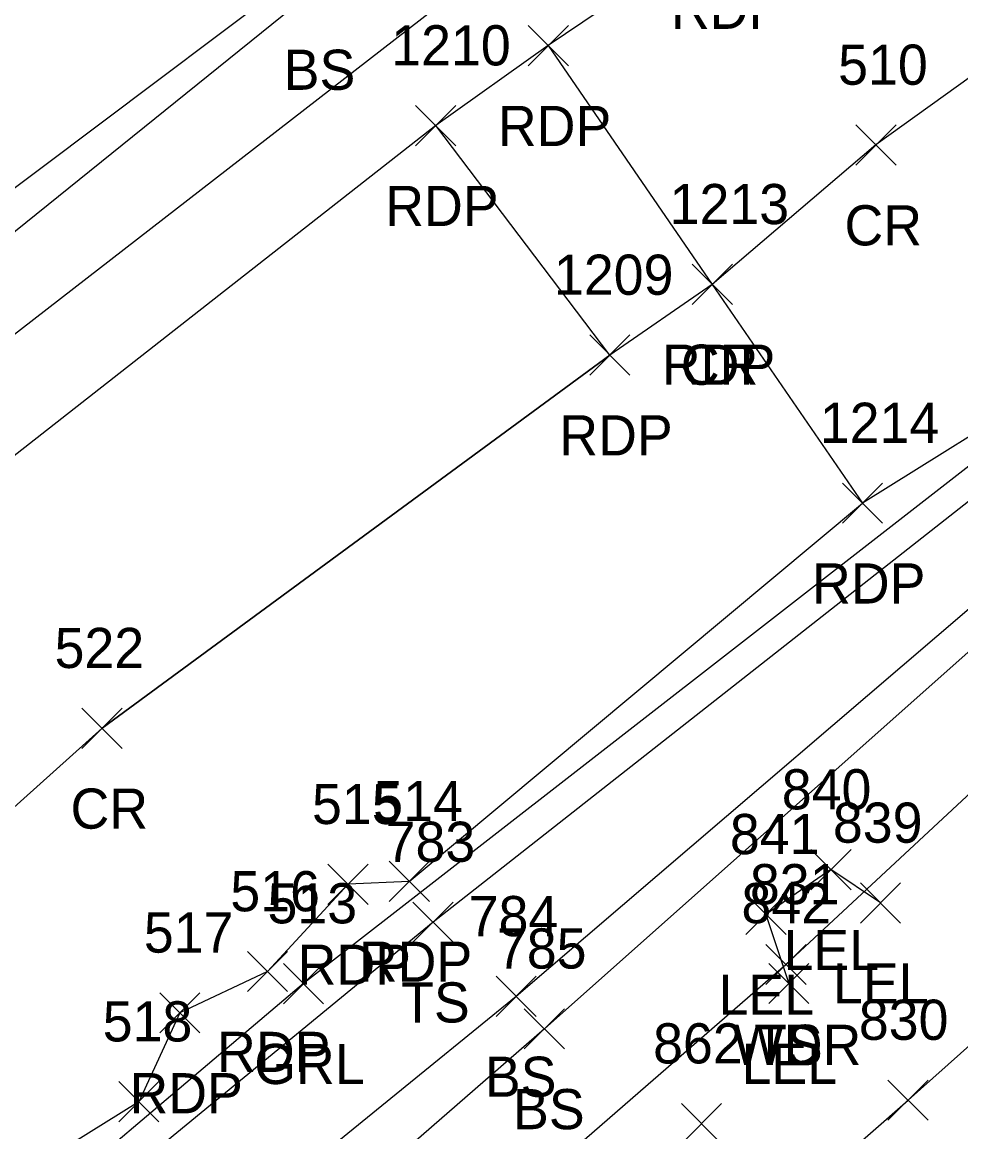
# Model space of a CAD drawing. Extents: x 1528286 to 1556263, y 492387 to 508952.
# Drawn here: x 1528541.2 to 1528588, y 492686.8 to 492742 of the extents above; entities that cross this region are included whole.
import ezdxf

# ---------------------------------------------------------------- set-up
doc = ezdxf.new("R2010")
doc.units = 0
for name, color, linetype in [('L_A', 7, 'Continuous'), ('L_I', 7, 'Continuous'), ('L_TIC', 7, 'Continuous'), ('LARO', 7, 'Continuous'), ('LAWA', 7, 'Continuous'), ('LELB', 7, 'Continuous'), ('P_A', 7, 'Continuous'), ('P_I', 7, 'Continuous'), ('P_TIC', 7, 'Continuous'), ('PET', 7, 'Continuous'), ('PRC', 7, 'Continuous'), ('R_A', 7, 'Continuous'), ('R_I', 7, 'Continuous'), ('R_TIC', 7, 'Continuous'), ('RGR', 7, 'Continuous')]:
    doc.layers.add(name, color=color, linetype=linetype)

msp = doc.modelspace()

# ---------------------------------------------------------------- linework, layer by layer
at = {"layer": 'L_TIC'}
for points in [[(1528580.51, 492698.848), (1528582.51, 492700.848)], [(1528582.51, 492698.848), (1528580.51, 492700.848)], [(1528580.51, 492698.848), (1528582.51, 492700.848)], [(1528582.51, 492698.848), (1528580.51, 492700.848)], [(1528582.976, 492697.188), (1528584.976, 492699.188)], [(1528584.976, 492697.188), (1528582.976, 492699.188)], [(1528582.976, 492697.188), (1528584.976, 492699.188)], [(1528584.976, 492697.188), (1528582.976, 492699.188)], [(1528577.273, 492696.621), (1528579.273, 492698.621)], [(1528579.273, 492696.621), (1528577.273, 492698.621)], [(1528577.273, 492696.621), (1528579.273, 492698.621)], [(1528579.273, 492696.621), (1528577.273, 492698.621)], [(1528560.7, 492696.236), (1528562.7, 492698.236)], [(1528562.7, 492696.236), (1528560.7, 492698.236)], [(1528560.7, 492696.236), (1528562.7, 492698.236)], [(1528562.7, 492696.236), (1528560.7, 492698.236)], [(1528578.271, 492694.125), (1528580.271, 492696.125)], [(1528580.271, 492694.125), (1528578.271, 492696.125)], [(1528578.271, 492694.125), (1528580.271, 492696.125)], [(1528580.271, 492694.125), (1528578.271, 492696.125)], [(1528578.271, 492694.125), (1528580.271, 492696.125)], [(1528580.271, 492694.125), (1528578.271, 492696.125)], [(1528578.271, 492694.125), (1528580.271, 492696.125)], [(1528580.271, 492694.125), (1528578.271, 492696.125)], [(1528578.416, 492693.181), (1528580.416, 492695.181)], [(1528580.416, 492693.181), (1528578.416, 492695.181)], [(1528578.416, 492693.181), (1528580.416, 492695.181)], [(1528580.416, 492693.181), (1528578.416, 492695.181)], [(1528564.837, 492692.535), (1528566.837, 492694.535)], [(1528566.837, 492692.535), (1528564.837, 492694.535)], [(1528564.837, 492692.535), (1528566.837, 492694.535)], [(1528566.837, 492692.535), (1528564.837, 492694.535)], [(1528566.241, 492690.922), (1528568.241, 492692.922)], [(1528568.241, 492690.922), (1528566.241, 492692.922)], [(1528566.241, 492690.922), (1528568.241, 492692.922)], [(1528568.241, 492690.922), (1528566.241, 492692.922)], [(1528584.347, 492687.372), (1528586.347, 492689.372)], [(1528586.347, 492687.372), (1528584.347, 492689.372)], [(1528584.347, 492687.372), (1528586.347, 492689.372)], [(1528586.347, 492687.372), (1528584.347, 492689.372)], [(1528574.065, 492686.197), (1528576.065, 492688.197)], [(1528576.065, 492686.197), (1528574.065, 492688.197)], [(1528574.065, 492686.197), (1528576.065, 492688.197)], [(1528576.065, 492686.197), (1528574.065, 492688.197)]]:
    msp.add_lwpolyline(points, dxfattribs=at)
at = {"layer": 'LARO'}
msp.add_lwpolyline([(1528583.976, 492698.188), (1528581.51, 492699.848), (1528578.273, 492697.621), (1528579.416, 492694.181)], dxfattribs=at)
msp.add_lwpolyline([(1528583.976, 492698.188), (1528581.51, 492699.848), (1528578.273, 492697.621), (1528579.416, 492694.181)], dxfattribs=at)
at = {"layer": 'LAWA'}
msp.add_lwpolyline([(1528350.567, 492486.658), (1528374.131, 492513.994), (1528413.925, 492550.925), (1528435.091, 492569.848), (1528453.537, 492583.197), (1528487.048, 492613.162), (1528503.178, 492626.813), (1528522.579, 492648.478), (1528559.072, 492677.555), (1528579.271, 492695.125), (1528598.445, 492712.961), (1528609.007, 492715.026)], dxfattribs=at)
msp.add_lwpolyline([(1528350.567, 492486.658), (1528374.131, 492513.994), (1528413.925, 492550.925), (1528435.091, 492569.848), (1528453.537, 492583.197), (1528487.048, 492613.162), (1528503.178, 492626.813), (1528522.579, 492648.478), (1528559.072, 492677.555), (1528579.271, 492695.125), (1528598.445, 492712.961), (1528609.007, 492715.026)], dxfattribs=at)
at = {"layer": 'LELB'}
for points in [[(1528511.531, 492702.846), (1528534.14, 492721.314), (1528572.642, 492751.164), (1528586.729, 492763.586), (1528600.497, 492766.346), (1528613.458, 492775.516), (1528652.2, 492802.526), (1528688.619, 492828.262), (1528710.289, 492843.118), (1528742.907, 492866.471), (1528778.713, 492891.266), (1528817.445, 492919.082), (1528857.746, 492946.937), (1528897.372, 492973.983), (1528940.286, 493003.739)], [(1528511.531, 492702.846), (1528534.14, 492721.314), (1528572.642, 492751.164), (1528586.729, 492763.586), (1528600.497, 492766.346), (1528613.458, 492775.516), (1528652.2, 492802.526), (1528688.619, 492828.262), (1528710.289, 492843.118), (1528742.907, 492866.471), (1528778.713, 492891.266), (1528817.445, 492919.082), (1528857.746, 492946.937), (1528897.372, 492973.983), (1528940.286, 493003.739)], [(1528476.47, 492733.086), (1528490.627, 492720.26), (1528499.344, 492715.307), (1528510.272, 492713.09), (1528516.407, 492713.286), (1528530.473, 492725.995), (1528568.475, 492754.562), (1528582.496, 492766.122), (1528590.696, 492769.852), (1528623.394, 492792.056), (1528660.048, 492816.01), (1528671.542, 492831.179), (1528678.095, 492847.611)], [(1528476.47, 492733.086), (1528490.627, 492720.26), (1528499.344, 492715.307), (1528510.272, 492713.09), (1528516.407, 492713.286), (1528530.473, 492725.995), (1528568.475, 492754.562), (1528582.496, 492766.122), (1528590.696, 492769.852), (1528623.394, 492792.056), (1528660.048, 492816.01), (1528671.542, 492831.179), (1528678.095, 492847.611)], [(1528685.936, 492838.575), (1528672.607, 492830.811), (1528666.617, 492820.24), (1528643.207, 492802.995), (1528614.904, 492783.769), (1528590.503, 492768.834), (1528580.049, 492763.591), (1528573.986, 492757.651), (1528555.822, 492743.679), (1528531.303, 492723.898), (1528516.93, 492710.506), (1528511.372, 492706.597)], [(1528685.936, 492838.575), (1528672.607, 492830.811), (1528666.617, 492820.24), (1528643.207, 492802.995), (1528614.904, 492783.769), (1528590.503, 492768.834), (1528580.049, 492763.591), (1528573.986, 492757.651), (1528555.822, 492743.679), (1528531.303, 492723.898), (1528516.93, 492710.506), (1528511.372, 492706.597)], [(1528627.535, 492747.197), (1528602.245, 492728.24), (1528590.919, 492720.18), (1528561.7, 492697.236), (1528528.44, 492669.894), (1528504.886, 492649.176), (1528486.55, 492633.133), (1528477.153, 492624.603), (1528462.188, 492611.303), (1528435.473, 492586.893), (1528420.499, 492573.078), (1528389.262, 492542.582), (1528363.671, 492517.292), (1528340.83, 492494.601)], [(1528627.535, 492747.197), (1528602.245, 492728.24), (1528590.919, 492720.18), (1528561.7, 492697.236), (1528528.44, 492669.894), (1528504.886, 492649.176), (1528486.55, 492633.133), (1528477.153, 492624.603), (1528462.188, 492611.303), (1528435.473, 492586.893), (1528420.499, 492573.078), (1528389.262, 492542.582), (1528363.671, 492517.292), (1528340.83, 492494.601)], [(1528608.223, 492722.999), (1528593.799, 492717.472), (1528565.837, 492693.535), (1528532.387, 492666.306), (1528510.922, 492648.814), (1528501.929, 492641.591)], [(1528608.223, 492722.999), (1528593.799, 492717.472), (1528565.837, 492693.535), (1528532.387, 492666.306), (1528510.922, 492648.814), (1528501.929, 492641.591)], [(1528608.107, 492719.723), (1528594.767, 492716.381), (1528567.241, 492691.922), (1528534.242, 492663.203), (1528520.965, 492652.416), (1528501.929, 492641.591)], [(1528608.107, 492719.723), (1528594.767, 492716.381), (1528567.241, 492691.922), (1528534.242, 492663.203), (1528520.965, 492652.416), (1528501.929, 492641.591)], [(1528495.396, 492632.327), (1528503.178, 492626.813), (1528527.225, 492642.12), (1528549.208, 492659.483), (1528567.953, 492673.117), (1528585.347, 492688.372), (1528604.063, 492705.044), (1528609.007, 492715.026)], [(1528495.396, 492632.327), (1528503.178, 492626.813), (1528527.225, 492642.12), (1528549.208, 492659.483), (1528567.953, 492673.117), (1528585.347, 492688.372), (1528604.063, 492705.044), (1528609.007, 492715.026)], [(1528507.297, 492637.674), (1528537.612, 492659.846), (1528559.072, 492677.555), (1528579.271, 492695.125), (1528598.445, 492712.961), (1528609.007, 492715.026)], [(1528507.297, 492637.674), (1528537.612, 492659.846), (1528559.072, 492677.555), (1528579.271, 492695.125), (1528598.445, 492712.961), (1528609.007, 492715.026)]]:
    msp.add_lwpolyline(points, dxfattribs=at)
at = {"layer": 'P_TIC'}
for points in [[(1528566.438, 492739.881), (1528568.438, 492741.881)], [(1528568.438, 492739.881), (1528566.438, 492741.881)], [(1528566.438, 492739.881), (1528568.438, 492741.881)], [(1528568.438, 492739.881), (1528566.438, 492741.881)], [(1528560.831, 492735.896), (1528562.831, 492737.896)], [(1528562.831, 492735.896), (1528560.831, 492737.896)], [(1528560.831, 492735.896), (1528562.831, 492737.896)], [(1528562.831, 492735.896), (1528560.831, 492737.896)], [(1528582.75, 492734.932), (1528584.75, 492736.932)], [(1528584.75, 492734.932), (1528582.75, 492736.932)], [(1528582.75, 492734.932), (1528584.75, 492736.932)], [(1528584.75, 492734.932), (1528582.75, 492736.932)], [(1528574.604, 492727.991), (1528576.604, 492729.991)], [(1528576.604, 492727.991), (1528574.604, 492729.991)], [(1528574.604, 492727.991), (1528576.604, 492729.991)], [(1528576.604, 492727.991), (1528574.604, 492729.991)], [(1528574.604, 492727.991), (1528576.604, 492729.991)], [(1528576.604, 492727.991), (1528574.604, 492729.991)], [(1528574.604, 492727.991), (1528576.604, 492729.991)], [(1528576.604, 492727.991), (1528574.604, 492729.991)], [(1528569.498, 492724.473), (1528571.498, 492726.473)], [(1528571.498, 492724.473), (1528569.498, 492726.473)], [(1528569.498, 492724.473), (1528571.498, 492726.473)], [(1528571.498, 492724.473), (1528569.498, 492726.473)], [(1528582.08, 492717.1), (1528584.08, 492719.1)], [(1528584.08, 492717.1), (1528582.08, 492719.1)], [(1528582.08, 492717.1), (1528584.08, 492719.1)], [(1528584.08, 492717.1), (1528582.08, 492719.1)], [(1528544.219, 492705.888), (1528546.219, 492707.888)], [(1528546.219, 492705.888), (1528544.219, 492707.888)], [(1528544.219, 492705.888), (1528546.219, 492707.888)], [(1528546.219, 492705.888), (1528544.219, 492707.888)], [(1528556.469, 492698.118), (1528558.469, 492700.118)], [(1528558.469, 492698.118), (1528556.469, 492700.118)], [(1528556.469, 492698.118), (1528558.469, 492700.118)], [(1528558.469, 492698.118), (1528556.469, 492700.118)], [(1528559.517, 492698.264), (1528561.517, 492700.264)], [(1528561.517, 492698.264), (1528559.517, 492700.264)], [(1528559.517, 492698.264), (1528561.517, 492700.264)], [(1528561.517, 492698.264), (1528559.517, 492700.264)], [(1528552.458, 492693.773), (1528554.458, 492695.773)], [(1528554.458, 492693.773), (1528552.458, 492695.773)], [(1528552.458, 492693.773), (1528554.458, 492695.773)], [(1528554.458, 492693.773), (1528552.458, 492695.773)], [(1528548.097, 492691.715), (1528550.097, 492693.715)], [(1528550.097, 492691.715), (1528548.097, 492693.715)], [(1528548.097, 492691.715), (1528550.097, 492693.715)], [(1528550.097, 492691.715), (1528548.097, 492693.715)], [(1528546.05, 492687.292), (1528548.05, 492689.292)], [(1528548.05, 492687.292), (1528546.05, 492689.292)], [(1528546.05, 492687.292), (1528548.05, 492689.292)], [(1528548.05, 492687.292), (1528546.05, 492689.292)]]:
    msp.add_lwpolyline(points, dxfattribs=at)
at = {"layer": 'PET'}
for points in [[(1528576.056, 492746.716), (1528567.438, 492740.881)], [(1528576.056, 492746.716), (1528567.438, 492740.881)], [(1528567.438, 492740.881), (1528561.831, 492736.896)], [(1528567.438, 492740.881), (1528561.831, 492736.896)], [(1528567.438, 492740.881), (1528575.604, 492728.991), (1528583.08, 492718.1)], [(1528567.438, 492740.881), (1528575.604, 492728.991), (1528583.08, 492718.1)], [(1528561.831, 492736.896), (1528536.991, 492717.453)], [(1528561.831, 492736.896), (1528536.991, 492717.453)], [(1528570.498, 492725.473), (1528561.831, 492736.896)], [(1528570.498, 492725.473), (1528561.831, 492736.896)], [(1528570.498, 492725.473), (1528545.219, 492706.888)], [(1528570.498, 492725.473), (1528545.219, 492706.888)], [(1528592.558, 492724.002), (1528583.08, 492718.1)], [(1528592.558, 492724.002), (1528583.08, 492718.1)], [(1528560.517, 492699.264), (1528583.08, 492718.1)], [(1528560.517, 492699.264), (1528583.08, 492718.1)], [(1528523.925, 492687.768), (1528545.219, 492706.888)], [(1528523.925, 492687.768), (1528545.219, 492706.888)], [(1528560.517, 492699.264), (1528557.469, 492699.118), (1528553.458, 492694.773), (1528549.097, 492692.715), (1528547.05, 492688.292), (1528537.757, 492682.515), (1528535.94, 492680.254), (1528535.911, 492679.061), (1528519.42, 492665.123), (1528485.647, 492635.106), (1528449.898, 492603.317), (1528443.292, 492597.221), (1528441.443, 492597.056), (1528433.939, 492590.577), (1528430.616, 492585.987), (1528412.089, 492568.516), (1528375.77, 492531.986), (1528339.078, 492496.271)], [(1528560.517, 492699.264), (1528557.469, 492699.118), (1528553.458, 492694.773), (1528549.097, 492692.715), (1528547.05, 492688.292), (1528537.757, 492682.515), (1528535.94, 492680.254), (1528535.911, 492679.061), (1528519.42, 492665.123), (1528485.647, 492635.106), (1528449.898, 492603.317), (1528443.292, 492597.221), (1528441.443, 492597.056), (1528433.939, 492590.577), (1528430.616, 492585.987), (1528412.089, 492568.516), (1528375.77, 492531.986), (1528339.078, 492496.271)]]:
    msp.add_lwpolyline(points, dxfattribs=at)
at = {"layer": 'PRC'}
for points in [[(1528622.148, 492763.521), (1528583.75, 492735.932)], [(1528622.148, 492763.521), (1528583.75, 492735.932)], [(1528583.75, 492735.932), (1528575.604, 492728.991)], [(1528583.75, 492735.932), (1528575.604, 492728.991)], [(1528575.604, 492728.991), (1528570.498, 492725.473)], [(1528575.604, 492728.991), (1528570.498, 492725.473)], [(1528545.219, 492706.888), (1528570.498, 492725.473)], [(1528545.219, 492706.888), (1528570.498, 492725.473)], [(1528545.219, 492706.888), (1528523.925, 492687.768)], [(1528545.219, 492706.888), (1528523.925, 492687.768)]]:
    msp.add_lwpolyline(points, dxfattribs=at)
at = {"layer": 'R_TIC'}
for points in [[(1528554.254, 492693.171), (1528556.254, 492695.171)], [(1528556.254, 492693.171), (1528554.254, 492695.171)], [(1528554.254, 492693.171), (1528556.254, 492695.171)], [(1528556.254, 492693.171), (1528554.254, 492695.171)]]:
    msp.add_lwpolyline(points, dxfattribs=at)
at = {"layer": 'RGR'}
msp.add_lwpolyline([(1528631.557, 492751.518), (1528593.228, 492723.7), (1528555.254, 492694.171), (1528520.288, 492664.562), (1528486.051, 492634.677), (1528450.283, 492602.919), (1528412.918, 492568.153), (1528376.626, 492531.198), (1528339.769, 492495.46)], dxfattribs=at)
msp.add_lwpolyline([(1528631.557, 492751.518), (1528593.228, 492723.7), (1528555.254, 492694.171), (1528520.288, 492664.562), (1528486.051, 492634.677), (1528450.283, 492602.919), (1528412.918, 492568.153), (1528376.626, 492531.198), (1528339.769, 492495.46)], dxfattribs=at)

# ---------------------------------------------------------------- texts
at = {"layer": 'L_A'}
for s, p in [('BS', (1528554.263, 492738.679)), ('BS', (1528554.263, 492738.679)), ('LEL', (1528579.148, 492694.848)), ('LEL', (1528579.148, 492694.848)), ('LEL', (1528581.614, 492693.188)), ('LEL', (1528581.614, 492693.188)), ('LEL', (1528575.911, 492692.621)), ('LEL', (1528575.911, 492692.621)), ('TS', (1528560.11, 492692.236)), ('TS', (1528560.11, 492692.236)), ('WDR', (1528576.634, 492690.125)), ('WDR', (1528576.634, 492690.125)), ('TS', (1528577.681, 492690.125)), ('TS', (1528577.681, 492690.125)), ('LEL', (1528577.054, 492689.181)), ('LEL', (1528577.054, 492689.181)), ('BS', (1528564.278, 492688.535)), ('BS', (1528564.278, 492688.535)), ('BS', (1528565.682, 492686.922)), ('BS', (1528565.682, 492686.922))]:
    msp.add_text(s, height=2, dxfattribs=at).set_placement(p)
at = {"layer": 'L_I'}
for s, p in [('840', (1528579.061, 492702.848)), ('840', (1528579.061, 492702.848)), ('839', (1528581.606, 492701.188)), ('839', (1528581.606, 492701.188)), ('783', (1528559.338, 492700.236)), ('783', (1528559.338, 492700.236)), ('841', (1528576.478, 492700.621)), ('841', (1528576.478, 492700.621)), ('831', (1528577.476, 492698.125)), ('831', (1528577.476, 492698.125)), ('831', (1528577.476, 492698.125)), ('831', (1528577.476, 492698.125)), ('842', (1528577.054, 492697.181)), ('842', (1528577.054, 492697.181)), ('784', (1528563.475, 492696.535)), ('784', (1528563.475, 492696.535)), ('785', (1528564.879, 492694.922)), ('785', (1528564.879, 492694.922)), ('830', (1528582.898, 492691.372)), ('830', (1528582.898, 492691.372)), ('862', (1528572.655, 492690.197)), ('862', (1528572.655, 492690.197))]:
    msp.add_text(s, height=2, dxfattribs=at).set_placement(p)
at = {"layer": 'P_A'}
for s, p in [('RDP', (1528573.544, 492741.716)), ('RDP', (1528573.544, 492741.716)), ('RDP', (1528564.926, 492735.881)), ('RDP', (1528564.926, 492735.881)), ('RDP', (1528559.319, 492731.896)), ('RDP', (1528559.319, 492731.896)), ('CR', (1528582.183, 492730.932)), ('CR', (1528582.183, 492730.932)), ('RDP', (1528573.092, 492723.991)), ('RDP', (1528573.092, 492723.991)), ('CR', (1528574.037, 492723.991)), ('CR', (1528574.037, 492723.991)), ('RDP', (1528567.986, 492720.473)), ('RDP', (1528567.986, 492720.473)), ('RDP', (1528580.568, 492713.1)), ('RDP', (1528580.568, 492713.1)), ('CR', (1528543.652, 492701.888)), ('CR', (1528543.652, 492701.888)), ('RDP', (1528554.957, 492694.118)), ('RDP', (1528554.957, 492694.118)), ('RDP', (1528558.005, 492694.264)), ('RDP', (1528558.005, 492694.264)), ('RDP', (1528550.947, 492689.773)), ('RDP', (1528550.947, 492689.773)), ('RDP', (1528546.585, 492687.715)), ('RDP', (1528546.585, 492687.715))]:
    msp.add_text(s, height=2, dxfattribs=at).set_placement(p)
at = {"layer": 'P_I'}
for s, p in [('1210', (1528559.618, 492739.896)), ('1210', (1528559.618, 492739.896)), ('510', (1528581.868, 492738.932)), ('510', (1528581.868, 492738.932)), ('1213', (1528573.478, 492731.991)), ('1213', (1528573.478, 492731.991)), ('1213', (1528573.478, 492731.991)), ('1213', (1528573.478, 492731.991)), ('1209', (1528567.719, 492728.473)), ('1209', (1528567.719, 492728.473)), ('1214', (1528580.954, 492721.1)), ('1214', (1528580.954, 492721.1)), ('522', (1528542.857, 492709.888)), ('522', (1528542.857, 492709.888)), ('515', (1528555.674, 492702.118)), ('515', (1528555.674, 492702.118)), ('514', (1528558.722, 492702.264)), ('514', (1528558.722, 492702.264)), ('516', (1528551.608, 492697.773)), ('516', (1528551.608, 492697.773)), ('517', (1528547.302, 492695.715)), ('517', (1528547.302, 492695.715)), ('518', (1528545.254, 492691.292)), ('518', (1528545.254, 492691.292))]:
    msp.add_text(s, height=2, dxfattribs=at).set_placement(p)
at = {"layer": 'R_A'}
msp.add_text('GRL', height=2, dxfattribs=at).set_placement((1528552.798, 492689.171))
msp.add_text('GRL', height=2, dxfattribs=at).set_placement((1528552.798, 492689.171))
at = {"layer": 'R_I'}
msp.add_text('513', height=2, dxfattribs=at).set_placement((1528553.459, 492697.171))
msp.add_text('513', height=2, dxfattribs=at).set_placement((1528553.459, 492697.171))

doc.saveas('drawing.dxf')
